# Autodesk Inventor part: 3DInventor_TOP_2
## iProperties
Created: 2006-11
Part Number: 3DInventor_TOP_2
Document SubType Name: Modeling
Designer: conardl1
Density: 1 g/cm^3
Translation Standard: STEP AP203
File Name: TOP_2
Preprocessor: PRO/ENGINEER BY PARAMETRIC TECHNOLOGY CORPORATION, 2004280
Postprocessor: Build: 211m, Release: 10 - Date: Fri 03/18/2005
Sent Units: MILLIMETERS
Uncertainty: 0.012359622908670001
DESCRIPTION: Top 2 Part (for diamond control pad)
MODELED_BY: L Conard
Author: conardl1
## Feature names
1. Base1
